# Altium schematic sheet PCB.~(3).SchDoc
size A
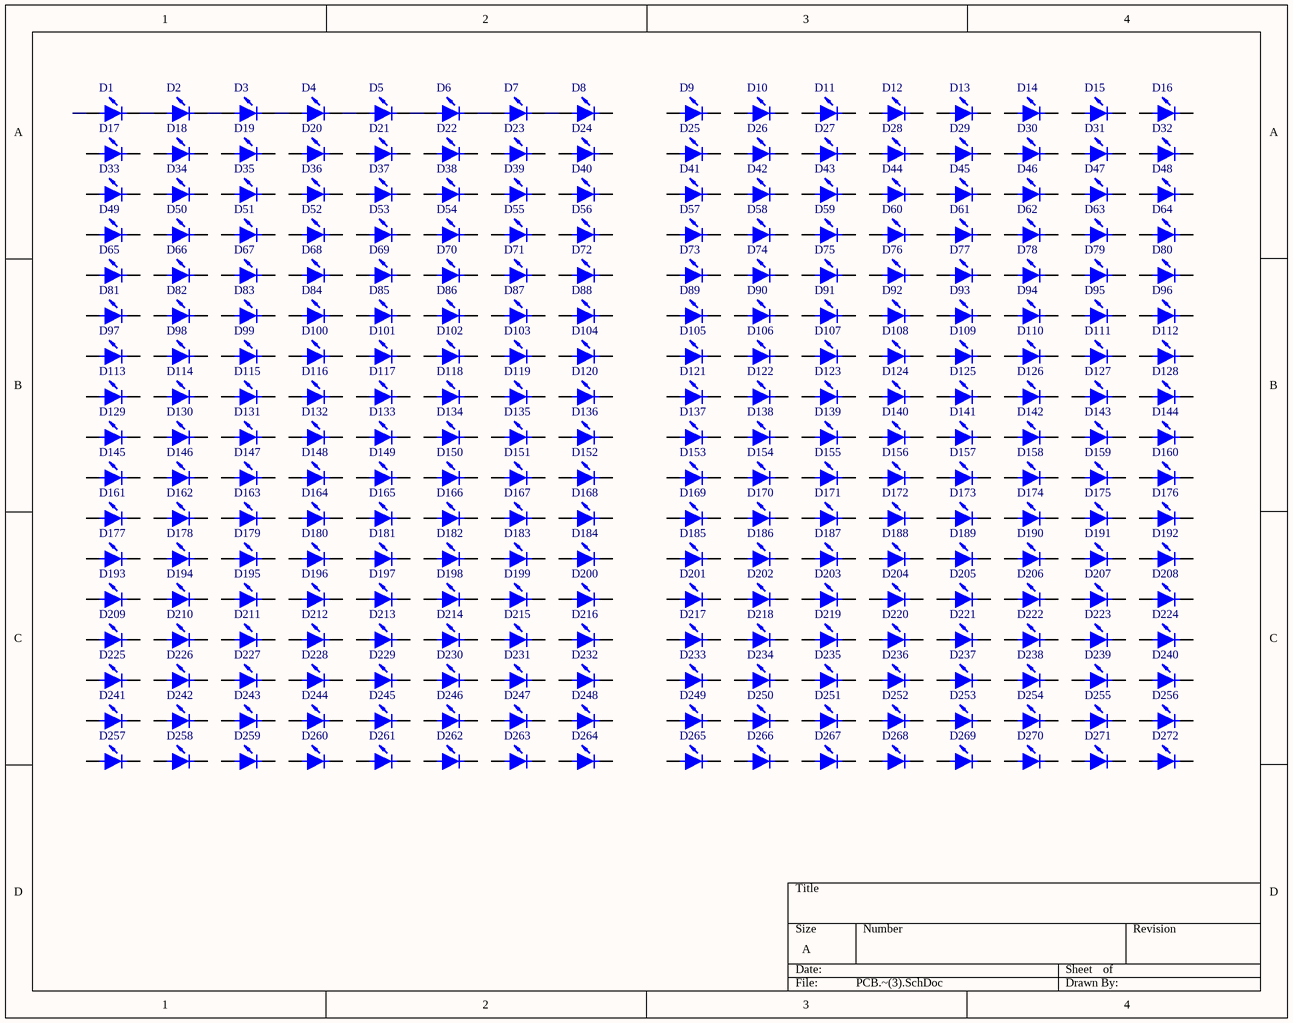
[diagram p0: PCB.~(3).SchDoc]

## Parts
D1  LED0  [LED-0]  (value not drawn)
D2  LED0  [LED-0]  (value not drawn)
D3  LED0  [LED-0]  (value not drawn)
D4  LED0  [LED-0]  (value not drawn)
D5  LED0  [LED-0]  (value not drawn)
D6  LED0  [LED-0]  (value not drawn)
D7  LED0  [LED-0]  (value not drawn)
D8  LED0  [LED-0]  (value not drawn)
D9  LED0  [LED-0]  (value not drawn)
D10  LED0  [LED-0]  (value not drawn)
D11  LED0  [LED-0]  (value not drawn)
D12  LED0  [LED-0]  (value not drawn)
D13  LED0  [LED-0]  (value not drawn)
D14  LED0  [LED-0]  (value not drawn)
D15  LED0  [LED-0]  (value not drawn)
D16  LED0  [LED-0]  (value not drawn)
D17  LED0  [LED-0]  (value not drawn)
D18  LED0  [LED-0]  (value not drawn)
D19  LED0  [LED-0]  (value not drawn)
D20  LED0  [LED-0]  (value not drawn)
D21  LED0  [LED-0]  (value not drawn)
D22  LED0  [LED-0]  (value not drawn)
D23  LED0  [LED-0]  (value not drawn)
D24  LED0  [LED-0]  (value not drawn)
D25  LED0  [LED-0]  (value not drawn)
D26  LED0  [LED-0]  (value not drawn)
D27  LED0  [LED-0]  (value not drawn)
D28  LED0  [LED-0]  (value not drawn)
D29  LED0  [LED-0]  (value not drawn)
D30  LED0  [LED-0]  (value not drawn)
D31  LED0  [LED-0]  (value not drawn)
D32  LED0  [LED-0]  (value not drawn)
D33  LED0  [LED-0]  (value not drawn)
D34  LED0  [LED-0]  (value not drawn)
D35  LED0  [LED-0]  (value not drawn)
D36  LED0  [LED-0]  (value not drawn)
D37  LED0  [LED-0]  (value not drawn)
D38  LED0  [LED-0]  (value not drawn)
D39  LED0  [LED-0]  (value not drawn)
D40  LED0  [LED-0]  (value not drawn)
D41  LED0  [LED-0]  (value not drawn)
D42  LED0  [LED-0]  (value not drawn)
D43  LED0  [LED-0]  (value not drawn)
D44  LED0  [LED-0]  (value not drawn)
D45  LED0  [LED-0]  (value not drawn)
D46  LED0  [LED-0]  (value not drawn)
D47  LED0  [LED-0]  (value not drawn)
D48  LED0  [LED-0]  (value not drawn)
D49  LED0  [LED-0]  (value not drawn)
D50  LED0  [LED-0]  (value not drawn)
D51  LED0  [LED-0]  (value not drawn)
D52  LED0  [LED-0]  (value not drawn)
D53  LED0  [LED-0]  (value not drawn)
D54  LED0  [LED-0]  (value not drawn)
D55  LED0  [LED-0]  (value not drawn)
D56  LED0  [LED-0]  (value not drawn)
D57  LED0  [LED-0]  (value not drawn)
D58  LED0  [LED-0]  (value not drawn)
D59  LED0  [LED-0]  (value not drawn)
D60  LED0  [LED-0]  (value not drawn)
D61  LED0  [LED-0]  (value not drawn)
D62  LED0  [LED-0]  (value not drawn)
D63  LED0  [LED-0]  (value not drawn)
D64  LED0  [LED-0]  (value not drawn)
D65  LED0  [LED-0]  (value not drawn)
D66  LED0  [LED-0]  (value not drawn)
D67  LED0  [LED-0]  (value not drawn)
D68  LED0  [LED-0]  (value not drawn)
D69  LED0  [LED-0]  (value not drawn)
D70  LED0  [LED-0]  (value not drawn)
D71  LED0  [LED-0]  (value not drawn)
D72  LED0  [LED-0]  (value not drawn)
D73  LED0  [LED-0]  (value not drawn)
D74  LED0  [LED-0]  (value not drawn)
D75  LED0  [LED-0]  (value not drawn)
D76  LED0  [LED-0]  (value not drawn)
D77  LED0  [LED-0]  (value not drawn)
D78  LED0  [LED-0]  (value not drawn)
D79  LED0  [LED-0]  (value not drawn)
D80  LED0  [LED-0]  (value not drawn)
D81  LED0  [LED-0]  (value not drawn)
D82  LED0  [LED-0]  (value not drawn)
D83  LED0  [LED-0]  (value not drawn)
D84  LED0  [LED-0]  (value not drawn)
D85  LED0  [LED-0]  (value not drawn)
D86  LED0  [LED-0]  (value not drawn)
D87  LED0  [LED-0]  (value not drawn)
D88  LED0  [LED-0]  (value not drawn)
D89  LED0  [LED-0]  (value not drawn)
D90  LED0  [LED-0]  (value not drawn)
D91  LED0  [LED-0]  (value not drawn)
D92  LED0  [LED-0]  (value not drawn)
D93  LED0  [LED-0]  (value not drawn)
D94  LED0  [LED-0]  (value not drawn)
D95  LED0  [LED-0]  (value not drawn)
D96  LED0  [LED-0]  (value not drawn)
D97  LED0  [LED-0]  (value not drawn)
D98  LED0  [LED-0]  (value not drawn)
D99  LED0  [LED-0]  (value not drawn)
D100  LED0  [LED-0]  (value not drawn)
D101  LED0  [LED-0]  (value not drawn)
D102  LED0  [LED-0]  (value not drawn)
D103  LED0  [LED-0]  (value not drawn)
D104  LED0  [LED-0]  (value not drawn)
D105  LED0  [LED-0]  (value not drawn)
D106  LED0  [LED-0]  (value not drawn)
D107  LED0  [LED-0]  (value not drawn)
D108  LED0  [LED-0]  (value not drawn)
D109  LED0  [LED-0]  (value not drawn)
D110  LED0  [LED-0]  (value not drawn)
D111  LED0  [LED-0]  (value not drawn)
D112  LED0  [LED-0]  (value not drawn)
D113  LED0  [LED-0]  (value not drawn)
D114  LED0  [LED-0]  (value not drawn)
D115  LED0  [LED-0]  (value not drawn)
D116  LED0  [LED-0]  (value not drawn)
D117  LED0  [LED-0]  (value not drawn)
D118  LED0  [LED-0]  (value not drawn)
D119  LED0  [LED-0]  (value not drawn)
D120  LED0  [LED-0]  (value not drawn)
D121  LED0  [LED-0]  (value not drawn)
D122  LED0  [LED-0]  (value not drawn)
D123  LED0  [LED-0]  (value not drawn)
D124  LED0  [LED-0]  (value not drawn)
D125  LED0  [LED-0]  (value not drawn)
D126  LED0  [LED-0]  (value not drawn)
D127  LED0  [LED-0]  (value not drawn)
D128  LED0  [LED-0]  (value not drawn)
D129  LED0  [LED-0]  (value not drawn)
D130  LED0  [LED-0]  (value not drawn)
D131  LED0  [LED-0]  (value not drawn)
D132  LED0  [LED-0]  (value not drawn)
D133  LED0  [LED-0]  (value not drawn)
D134  LED0  [LED-0]  (value not drawn)
D135  LED0  [LED-0]  (value not drawn)
D136  LED0  [LED-0]  (value not drawn)
D137  LED0  [LED-0]  (value not drawn)
D138  LED0  [LED-0]  (value not drawn)
D139  LED0  [LED-0]  (value not drawn)
D140  LED0  [LED-0]  (value not drawn)
D141  LED0  [LED-0]  (value not drawn)
D142  LED0  [LED-0]  (value not drawn)
D143  LED0  [LED-0]  (value not drawn)
D144  LED0  [LED-0]  (value not drawn)
D145  LED0  [LED-0]  (value not drawn)
D146  LED0  [LED-0]  (value not drawn)
D147  LED0  [LED-0]  (value not drawn)
D148  LED0  [LED-0]  (value not drawn)
D149  LED0  [LED-0]  (value not drawn)
D150  LED0  [LED-0]  (value not drawn)
D151  LED0  [LED-0]  (value not drawn)
D152  LED0  [LED-0]  (value not drawn)
D153  LED0  [LED-0]  (value not drawn)
D154  LED0  [LED-0]  (value not drawn)
D155  LED0  [LED-0]  (value not drawn)
D156  LED0  [LED-0]  (value not drawn)
D157  LED0  [LED-0]  (value not drawn)
D158  LED0  [LED-0]  (value not drawn)
D159  LED0  [LED-0]  (value not drawn)
D160  LED0  [LED-0]  (value not drawn)
D161  LED0  [LED-0]  (value not drawn)
D162  LED0  [LED-0]  (value not drawn)
D163  LED0  [LED-0]  (value not drawn)
D164  LED0  [LED-0]  (value not drawn)
D165  LED0  [LED-0]  (value not drawn)
D166  LED0  [LED-0]  (value not drawn)
D167  LED0  [LED-0]  (value not drawn)
D168  LED0  [LED-0]  (value not drawn)
D169  LED0  [LED-0]  (value not drawn)
D170  LED0  [LED-0]  (value not drawn)
D171  LED0  [LED-0]  (value not drawn)
D172  LED0  [LED-0]  (value not drawn)
D173  LED0  [LED-0]  (value not drawn)
D174  LED0  [LED-0]  (value not drawn)
D175  LED0  [LED-0]  (value not drawn)
D176  LED0  [LED-0]  (value not drawn)
D177  LED0  [LED-0]  (value not drawn)
D178  LED0  [LED-0]  (value not drawn)
D179  LED0  [LED-0]  (value not drawn)
D180  LED0  [LED-0]  (value not drawn)
D181  LED0  [LED-0]  (value not drawn)
D182  LED0  [LED-0]  (value not drawn)
D183  LED0  [LED-0]  (value not drawn)
D184  LED0  [LED-0]  (value not drawn)
D185  LED0  [LED-0]  (value not drawn)
D186  LED0  [LED-0]  (value not drawn)
D187  LED0  [LED-0]  (value not drawn)
D188  LED0  [LED-0]  (value not drawn)
D189  LED0  [LED-0]  (value not drawn)
D190  LED0  [LED-0]  (value not drawn)
D191  LED0  [LED-0]  (value not drawn)
D192  LED0  [LED-0]  (value not drawn)
D193  LED0  [LED-0]  (value not drawn)
D194  LED0  [LED-0]  (value not drawn)
D195  LED0  [LED-0]  (value not drawn)
D196  LED0  [LED-0]  (value not drawn)
D197  LED0  [LED-0]  (value not drawn)
D198  LED0  [LED-0]  (value not drawn)
D199  LED0  [LED-0]  (value not drawn)
D200  LED0  [LED-0]  (value not drawn)
D201  LED0  [LED-0]  (value not drawn)
D202  LED0  [LED-0]  (value not drawn)
D203  LED0  [LED-0]  (value not drawn)
D204  LED0  [LED-0]  (value not drawn)
D205  LED0  [LED-0]  (value not drawn)
D206  LED0  [LED-0]  (value not drawn)
D207  LED0  [LED-0]  (value not drawn)
D208  LED0  [LED-0]  (value not drawn)
D209  LED0  [LED-0]  (value not drawn)
D210  LED0  [LED-0]  (value not drawn)
D211  LED0  [LED-0]  (value not drawn)
D212  LED0  [LED-0]  (value not drawn)
D213  LED0  [LED-0]  (value not drawn)
D214  LED0  [LED-0]  (value not drawn)
D215  LED0  [LED-0]  (value not drawn)
D216  LED0  [LED-0]  (value not drawn)
D217  LED0  [LED-0]  (value not drawn)
D218  LED0  [LED-0]  (value not drawn)
D219  LED0  [LED-0]  (value not drawn)
D220  LED0  [LED-0]  (value not drawn)
D221  LED0  [LED-0]  (value not drawn)
D222  LED0  [LED-0]  (value not drawn)
D223  LED0  [LED-0]  (value not drawn)
D224  LED0  [LED-0]  (value not drawn)
D225  LED0  [LED-0]  (value not drawn)
D226  LED0  [LED-0]  (value not drawn)
D227  LED0  [LED-0]  (value not drawn)
D228  LED0  [LED-0]  (value not drawn)
D229  LED0  [LED-0]  (value not drawn)
D230  LED0  [LED-0]  (value not drawn)
D231  LED0  [LED-0]  (value not drawn)
D232  LED0  [LED-0]  (value not drawn)
D233  LED0  [LED-0]  (value not drawn)
D234  LED0  [LED-0]  (value not drawn)
D235  LED0  [LED-0]  (value not drawn)
D236  LED0  [LED-0]  (value not drawn)
D237  LED0  [LED-0]  (value not drawn)
D238  LED0  [LED-0]  (value not drawn)
D239  LED0  [LED-0]  (value not drawn)
D240  LED0  [LED-0]  (value not drawn)
D241  LED0  [LED-0]  (value not drawn)
D242  LED0  [LED-0]  (value not drawn)
D243  LED0  [LED-0]  (value not drawn)
D244  LED0  [LED-0]  (value not drawn)
D245  LED0  [LED-0]  (value not drawn)
D246  LED0  [LED-0]  (value not drawn)
D247  LED0  [LED-0]  (value not drawn)
D248  LED0  [LED-0]  (value not drawn)
D249  LED0  [LED-0]  (value not drawn)
D250  LED0  [LED-0]  (value not drawn)
D251  LED0  [LED-0]  (value not drawn)
D252  LED0  [LED-0]  (value not drawn)
D253  LED0  [LED-0]  (value not drawn)
D254  LED0  [LED-0]  (value not drawn)
D255  LED0  [LED-0]  (value not drawn)
D256  LED0  [LED-0]  (value not drawn)
D257  LED0  [LED-0]  (value not drawn)
D258  LED0  [LED-0]  (value not drawn)
D259  LED0  [LED-0]  (value not drawn)
D260  LED0  [LED-0]  (value not drawn)
D261  LED0  [LED-0]  (value not drawn)
D262  LED0  [LED-0]  (value not drawn)
D263  LED0  [LED-0]  (value not drawn)
D264  LED0  [LED-0]  (value not drawn)
D265  LED0  [LED-0]  (value not drawn)
D266  LED0  [LED-0]  (value not drawn)
D267  LED0  [LED-0]  (value not drawn)
D268  LED0  [LED-0]  (value not drawn)
D269  LED0  [LED-0]  (value not drawn)
D270  LED0  [LED-0]  (value not drawn)
D271  LED0  [LED-0]  (value not drawn)
D272  LED0  [LED-0]  (value not drawn)

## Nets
NetD1_2: D1.2(K) D2.1(A)
NetD2_2: D2.2(K) D3.1(A)
NetD3_2: D3.2(K) D4.1(A)
NetD4_2: D4.2(K) D5.1(A)
NetD5_2: D5.2(K) D6.1(A)
NetD6_2: D6.2(K) D7.1(A)
NetD7_2: D7.2(K) D8.1(A)

Not connected (* = marked no-connect by the designer): D1 1(A); D8 2(K); D9 1(A) 2(K); D10 1(A) 2(K); D11 1(A) 2(K); D12 1(A) 2(K); D13 1(A) 2(K); D14 1(A) 2(K); D15 1(A) 2(K); D16 1(A) 2(K); D17 1(A) 2(K); D18 1(A) 2(K); D19 1(A) 2(K); D20 1(A) 2(K); D21 1(A) 2(K); D22 1(A) 2(K); D23 1(A) 2(K); D24 1(A) 2(K); D25 1(A) 2(K); D26 1(A) 2(K); D27 1(A) 2(K); D28 1(A) 2(K); D29 1(A) 2(K); D30 1(A) 2(K); D31 1(A) 2(K); D32 1(A) 2(K); D33 1(A) 2(K); D34 1(A) 2(K); D35 1(A) 2(K); D36 1(A) 2(K); D37 1(A) 2(K); D38 1(A) 2(K); D39 1(A) 2(K); D40 1(A) 2(K); D41 1(A) 2(K); D42 1(A) 2(K); D43 1(A) 2(K); D44 1(A) 2(K); D45 1(A) 2(K); D46 1(A) 2(K); D47 1(A) 2(K); D48 1(A) 2(K); D49 1(A) 2(K); D50 1(A) 2(K); D51 1(A) 2(K); D52 1(A) 2(K); D53 1(A) 2(K); D54 1(A) 2(K); D55 1(A) 2(K); D56 1(A) 2(K); D57 1(A) 2(K); D58 1(A) 2(K); D59 1(A) 2(K); D60 1(A) 2(K); D61 1(A) 2(K); D62 1(A) 2(K); D63 1(A) 2(K); D64 1(A) 2(K); D65 1(A) 2(K); D66 1(A) 2(K); D67 1(A) 2(K); D68 1(A) 2(K); D69 1(A) 2(K); D70 1(A) 2(K); D71 1(A) 2(K); D72 1(A) 2(K); D73 1(A) 2(K); D74 1(A) 2(K); D75 1(A) 2(K); D76 1(A) 2(K); D77 1(A) 2(K); D78 1(A) 2(K); D79 1(A) 2(K); D80 1(A) 2(K); D81 1(A) 2(K); D82 1(A) 2(K); D83 1(A) 2(K); D84 1(A) 2(K); D85 1(A) 2(K); D86 1(A) 2(K); D87 1(A) 2(K); D88 1(A) 2(K); D89 1(A) 2(K); D90 1(A) 2(K); D91 1(A) 2(K); D92 1(A) 2(K); D93 1(A) 2(K); D94 1(A) 2(K); D95 1(A) 2(K); D96 1(A) 2(K); D97 1(A) 2(K); D98 1(A) 2(K); D99 1(A) 2(K); D100 1(A) 2(K); D101 1(A) 2(K); D102 1(A) 2(K); D103 1(A) 2(K); D104 1(A) 2(K); D105 1(A) 2(K); D106 1(A) 2(K); D107 1(A) 2(K); D108 1(A) 2(K); D109 1(A) 2(K); D110 1(A) 2(K); D111 1(A) 2(K); D112 1(A) 2(K); D113 1(A) 2(K); D114 1(A) 2(K); D115 1(A) 2(K); D116 1(A) 2(K); D117 1(A) 2(K); D118 1(A) 2(K); D119 1(A) 2(K); D120 1(A) 2(K); D121 1(A) 2(K); D122 1(A) 2(K); D123 1(A) 2(K); D124 1(A) 2(K); D125 1(A) 2(K); D126 1(A) 2(K); D127 1(A) 2(K); D128 1(A) 2(K); D129 1(A) 2(K); D130 1(A) 2(K); D131 1(A) 2(K); D132 1(A) 2(K); D133 1(A) 2(K); D134 1(A) 2(K); D135 1(A) 2(K); D136 1(A) 2(K); D137 1(A) 2(K); D138 1(A) 2(K); D139 1(A) 2(K); D140 1(A) 2(K); D141 1(A) 2(K); D142 1(A) 2(K); D143 1(A) 2(K); D144 1(A) 2(K); D145 1(A) 2(K); D146 1(A) 2(K); D147 1(A) 2(K); D148 1(A) 2(K); D149 1(A) 2(K); D150 1(A) 2(K); D151 1(A) 2(K); D152 1(A) 2(K); D153 1(A) 2(K); D154 1(A) 2(K); D155 1(A) 2(K); D156 1(A) 2(K); D157 1(A) 2(K); D158 1(A) 2(K); D159 1(A) 2(K); D160 1(A) 2(K); D161 1(A) 2(K); D162 1(A) 2(K); D163 1(A) 2(K); D164 1(A) 2(K); D165 1(A) 2(K); D166 1(A) 2(K); D167 1(A) 2(K); D168 1(A) 2(K); D169 1(A) 2(K); D170 1(A) 2(K); D171 1(A) 2(K); D172 1(A) 2(K); D173 1(A) 2(K); D174 1(A) 2(K); D175 1(A) 2(K); D176 1(A) 2(K); D177 1(A) 2(K); D178 1(A) 2(K); D179 1(A) 2(K); D180 1(A) 2(K); D181 1(A) 2(K); D182 1(A) 2(K); D183 1(A) 2(K); D184 1(A) 2(K); D185 1(A) 2(K); D186 1(A) 2(K); D187 1(A) 2(K); D188 1(A) 2(K); D189 1(A) 2(K); D190 1(A) 2(K); D191 1(A) 2(K); D192 1(A) 2(K); D193 1(A) 2(K); D194 1(A) 2(K); D195 1(A) 2(K); D196 1(A) 2(K); D197 1(A) 2(K); D198 1(A) 2(K); D199 1(A) 2(K); D200 1(A) 2(K); D201 1(A) 2(K); D202 1(A) 2(K); D203 1(A) 2(K); D204 1(A) 2(K); D205 1(A) 2(K); D206 1(A) 2(K); D207 1(A) 2(K); D208 1(A) 2(K); D209 1(A) 2(K); D210 1(A) 2(K); D211 1(A) 2(K); D212 1(A) 2(K); D213 1(A) 2(K); D214 1(A) 2(K); D215 1(A) 2(K); D216 1(A) 2(K); D217 1(A) 2(K); D218 1(A) 2(K); D219 1(A) 2(K); D220 1(A) 2(K); D221 1(A) 2(K); D222 1(A) 2(K); D223 1(A) 2(K); D224 1(A) 2(K); D225 1(A) 2(K); D226 1(A) 2(K); D227 1(A) 2(K); D228 1(A) 2(K); D229 1(A) 2(K); D230 1(A) 2(K); D231 1(A) 2(K); D232 1(A) 2(K); D233 1(A) 2(K); D234 1(A) 2(K); D235 1(A) 2(K); D236 1(A) 2(K); D237 1(A) 2(K); D238 1(A) 2(K); D239 1(A) 2(K); D240 1(A) 2(K); D241 1(A) 2(K); D242 1(A) 2(K); D243 1(A) 2(K); D244 1(A) 2(K); D245 1(A) 2(K); D246 1(A) 2(K); D247 1(A) 2(K); D248 1(A) 2(K); D249 1(A) 2(K); D250 1(A) 2(K); D251 1(A) 2(K); D252 1(A) 2(K); D253 1(A) 2(K); D254 1(A) 2(K); D255 1(A) 2(K); D256 1(A) 2(K); D257 1(A) 2(K); D258 1(A) 2(K); D259 1(A) 2(K); D260 1(A) 2(K); D261 1(A) 2(K); D262 1(A) 2(K); D263 1(A) 2(K); D264 1(A) 2(K); D265 1(A) 2(K); D266 1(A) 2(K); D267 1(A) 2(K); D268 1(A) 2(K); D269 1(A) 2(K); D270 1(A) 2(K); D271 1(A) 2(K); D272 1(A) 2(K)

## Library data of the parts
D1-D272 = LED0: Typical INFRARED GaAs LED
